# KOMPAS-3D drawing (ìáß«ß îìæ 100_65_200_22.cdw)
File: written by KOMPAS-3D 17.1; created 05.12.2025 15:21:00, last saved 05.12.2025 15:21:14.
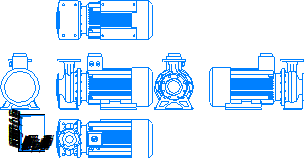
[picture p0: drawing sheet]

Sheet 1: A4, portrait

Title block, sheet 1: name: Насос МНС / 100_65_200_22; material: Сталь 10  ГОСТ 1050-88; mass: 330,84; sheets: 1; sheet format: A4

Views: Вид 1, Спереди, Проекционный вид 2, Проекционный вид 3, Проекционный вид 4, Проекционный вид 5, Проекционный вид 6
Referenced files in \\adlc.lan\data\АДЛ_ПКД\3D-модели\ADL production\Насосы ГРАНПАМП\Насосы ГРАНПАМП серии МНС\KOMPAS 3D\: Насос МНС 100-65-200_22.m3d
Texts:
  Andrey
  АДЛ
Dimensions and other numbers on the sheet: 1:1; 1; 100_65_200_22; 330,84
